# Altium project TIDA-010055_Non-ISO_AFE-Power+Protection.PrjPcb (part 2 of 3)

## Sheet TIDA-010055_Non-ISO_AFE-Power+Protection _Pg5.SchDoc: ISOLATED AFE SUPPLY , LDOs
size 431 x 279 mm; Date: Not shown in title block; ApprovedBy: Not shown in title block; CheckedBy: Not shown in title block; Author: Not shown in title block; CompanyName: Not shown in title block; DrawnBy: Sreenivasa; Engineer: Not shown in title block; Organization: Not shown in title block; Address1: Not shown in title block; Address2: Not shown in title block; Address3: Not shown in title block; Address4: Not shown in title block; DocumentNumber: 1; Revision: Use project parameter SCH_Rev; SheetNumber: 5; SheetTotal: 9; PageSetup: Record=PageOptions¦CenterHorizontal=True¦CenterVertical=True¦PrintScale=0.62¦XCorrection=1.00¦YCorrection=1.00¦PrintKind=0¦BorderSize=5000000¦LeftOffset=0¦BottomOffset=0¦Orientation=2¦PaperLength=1000¦PaperWidth=1000¦Scale=100¦PaperSource=15¦PrintQuality=600¦MediaType=1¦DitherType=10¦PrintScaleMode=1¦PaperKind=Letter
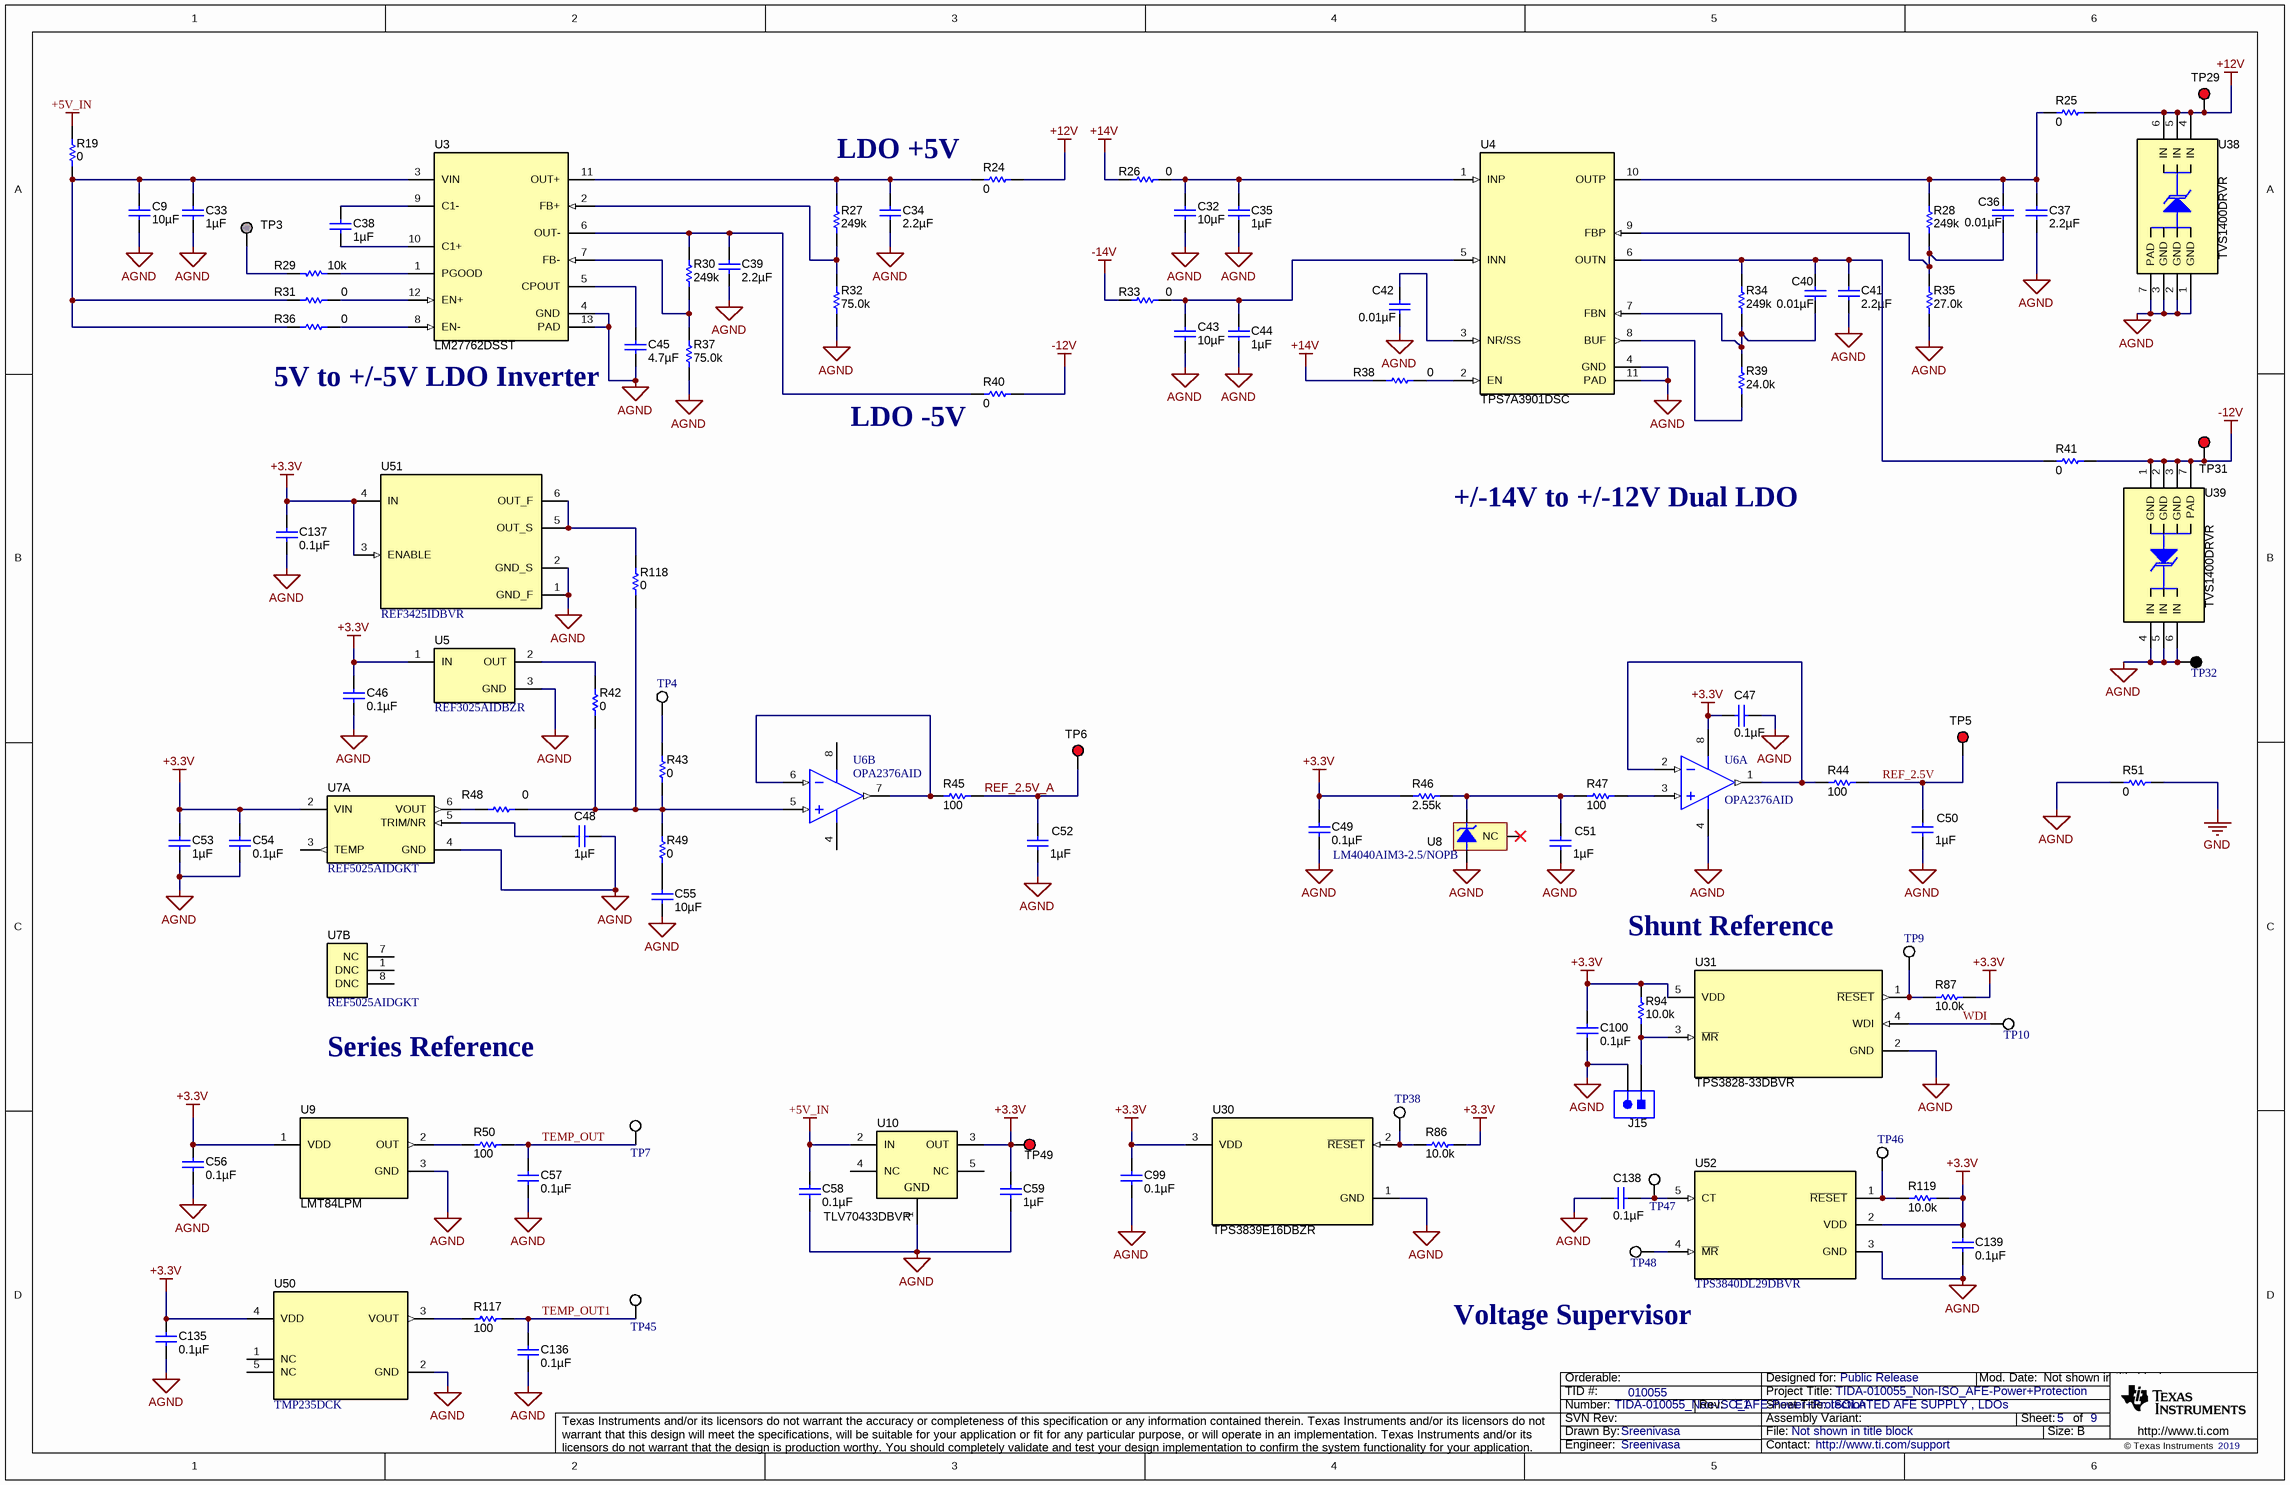
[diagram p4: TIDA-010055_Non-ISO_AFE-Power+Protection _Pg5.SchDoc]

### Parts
C9  ValueDisplayed: 10µF  [1210]
C32  ValueDisplayed: 10µF  [1210]
C33  ValueDisplayed: 1µF  [0603S]  (hidden comment: CGA3E1X7R1E105K080AC)
C34  ValueDisplayed: 2.2µF  [0805_HV]  (hidden comment: C0805C225K8RACTU)
C35  ValueDisplayed: 1µF  [0603S]  (hidden comment: CGA3E1X7R1E105K080AC)
C36  ValueDisplayed: 0.01µF  [0603]  (hidden comment: 885012206040)
C37  ValueDisplayed: 2.2µF  [0805_HV]  (hidden comment: C0805C225K8RACTU)
C38  ValueDisplayed: 1µF  [0603S]  (hidden comment: CGA3E1X7R1E105K080AC)
C39  ValueDisplayed: 2.2µF  [0805_HV]  (hidden comment: C0805C225K8RACTU)
C40  ValueDisplayed: 0.01µF  [0603]  (hidden comment: 885012206040)
C41  ValueDisplayed: 2.2µF  [0805_HV]  (hidden comment: C0805C225K8RACTU)
C42  ValueDisplayed: 0.01µF  [0603]  (hidden comment: 885012206040)
C43  ValueDisplayed: 10µF  [1210]
C44  ValueDisplayed: 1µF  [0603S]  (hidden comment: CGA3E1X7R1E105K080AC)
C45  ValueDisplayed: 4.7µF  [1206]  (hidden comment: C3216X7R1E475M160AC)
C46  ValueDisplayed: 0.1µF  [0603]  (hidden comment: 06033D104KAT2A)
C47  ValueDisplayed: 0.1µF  [0603]  (hidden comment: 06033D104KAT2A)
C48  ValueDisplayed: 1µF  [0805_HV]  (hidden comment: CL21B105KPFNNNE)
C49  ValueDisplayed: 0.1µF  [0603]  (hidden comment: 06033D104KAT2A)
C50  ValueDisplayed: 1µF  [0805_HV]  (hidden comment: C2012X7R1H105K125AE)
C51  ValueDisplayed: 1µF  [0805_HV]  (hidden comment: C2012X7R1H105K125AE)
C52  ValueDisplayed: 1µF  [0805_HV]  (hidden comment: C2012X7R1H105K125AE)
C53  ValueDisplayed: 1µF  [0805_HV]  (hidden comment: CL21B105KPFNNNE)
C54  ValueDisplayed: 0.1µF  [0603]  (hidden comment: 06033D104KAT2A)
C55  ValueDisplayed: 10µF  [0603]  (hidden comment: EMK107BBJ106MA-T)
C56  ValueDisplayed: 0.1µF  [0603]  (hidden comment: 06033D104KAT2A)
C57  ValueDisplayed: 0.1µF  [0603]  (hidden comment: 06033D104KAT2A)
C58  ValueDisplayed: 0.1µF  [0603]  (hidden comment: 06033D104KAT2A)
C59  ValueDisplayed: 1µF  [0603]  (hidden comment: CGB3B3X7R0J105K055AB)
C99  ValueDisplayed: 0.1µF  [0603]  (hidden comment: 06033D104KAT2A)
C100  ValueDisplayed: 0.1µF  [0603]  (hidden comment: 06033D104KAT2A)
C135  ValueDisplayed: 0.1µF  [0603]  (hidden comment: 06033D104KAT2A)
C136  ValueDisplayed: 0.1µF  [0603]  (hidden comment: 06033D104KAT2A)
C137  ValueDisplayed: 0.1µF  [0603]  (hidden comment: 06033D104KAT2A)
C138  ValueDisplayed: 0.1µF  [0603]  (hidden comment: 06033D104KAT2A)
C139  ValueDisplayed: 0.1µF  [0603]  (hidden comment: 06033D104KAT2A)
J15  PBC02SAAN  [Sullins_PBC02SAAN]  (value not drawn)
R19  ValueDisplayed: 0  [1206]  (hidden comment: CRCW12060000Z0EA)
R24  ValueDisplayed: 0  [0603]  (hidden comment: CRCW06030000Z0EA)
R25  ValueDisplayed: 0  [0603]  (hidden comment: CRCW06030000Z0EA)
R26  ValueDisplayed: 0  [0603]  (hidden comment: CRCW06030000Z0EA)
R27  ValueDisplayed: 249k  [0603]  (hidden comment: CRCW0603249KFKEA)
R28  ValueDisplayed: 249k  [0603]  (hidden comment: CRCW0603249KFKEA)
R29  value 10k  [0603]  (hidden comment: CRCW060310K0FKEA)
R30  ValueDisplayed: 249k  [0603]  (hidden comment: CRCW0603249KFKEA)
R31  ValueDisplayed: 0  [0603]  (hidden comment: CRCW06030000Z0EA)
R32  ValueDisplayed: 75.0k  [0603]  (hidden comment: CRCW060375K0FKEA)
R33  ValueDisplayed: 0  [0603]  (hidden comment: CRCW06030000Z0EA)
R34  ValueDisplayed: 249k  [0603]  (hidden comment: CRCW0603249KFKEA)
R35  ValueDisplayed: 27.0k  [0603]  (hidden comment: RC0603FR-0727KL)
R36  ValueDisplayed: 0  [0603]  (hidden comment: CRCW06030000Z0EA)
R37  ValueDisplayed: 75.0k  [0603]  (hidden comment: CRCW060375K0FKEA)
R38  ValueDisplayed: 0  [0603]  (hidden comment: CRCW06030000Z0EA)
R39  ValueDisplayed: 24.0k  [0603]  (hidden comment: RC0603FR-0724KL)
R40  ValueDisplayed: 0  [0603]  (hidden comment: CRCW06030000Z0EA)
R41  ValueDisplayed: 0  [0603]  (hidden comment: CRCW06030000Z0EA)
R42  value 0  [0603]  (hidden comment: CRCW06030000Z0EA)
R43  value 0  [0603]  (hidden comment: CRCW06030000Z0EA)
R44  ValueDisplayed: 100  [0603]  (hidden comment: CRCW0603100RFKEA)
R45  ValueDisplayed: 100  [0603]  (hidden comment: CRCW0603100RFKEA)
R46  ValueDisplayed: 2.55k  [0603]  (hidden comment: CRCW06032K55FKEA)
R47  ValueDisplayed: 100  [0603]  (hidden comment: CRCW0603100RFKEA)
R48  value 0  [0603]  (hidden comment: CRCW06030000Z0EA)
R49  value 0  [0603]  (hidden comment: CRCW06030000Z0EA)
R50  ValueDisplayed: 100  [0603]  (hidden comment: CRCW0603100RFKEA)
R51  ValueDisplayed: 0  [1206]  (hidden comment: RC1206JR-070RL)
R86  ValueDisplayed: 10.0k  [0603]  (hidden comment: RC0603FR-0710KL)
R87  ValueDisplayed: 10.0k  [0603]  (hidden comment: RC0603FR-0710KL)
R94  ValueDisplayed: 10.0k  [0603]  (hidden comment: RC0603FR-0710KL)
R117  ValueDisplayed: 100  [0603]  (hidden comment: CRCW0603100RFKEA)
R118  value 0  [0603]  (hidden comment: CRCW06030000Z0EA)
R119  ValueDisplayed: 10.0k  [0603]  (hidden comment: RC0603FR-0710KL)
TP3  Pogo Pad  [PogoPad]  (value not drawn)  (no BOM)
TP4  5002  [Keystone5002]  (value not drawn)
TP5  5000  [Keystone5000]  (value not drawn)
TP6  5000  [Keystone5000]  (value not drawn)
TP7  5002  [Keystone5002]  (value not drawn)
TP9  5002  [Keystone5002]  (value not drawn)
TP10  5002  [Keystone5002]  (value not drawn)
TP29  5000  [Keystone5000]  (value not drawn)
TP31  5000  [Keystone5000]  (value not drawn)
TP32  5001  [Keystone5001]  (value not drawn)
TP38  5002  [Keystone5002]  (value not drawn)
TP45  5002  [Keystone5002]  (value not drawn)
TP46  5002  [Keystone5002]  (value not drawn)
TP47  5002  [Keystone5002]  (value not drawn)
TP48  5002  [Keystone5002]  (value not drawn)
TP49  5000  [Keystone5000]  (value not drawn)
U3  LM27762DSST  [DSS0012B]
U4  TPS7A3901DSC  [DSC0010J]
U5  REF3025AIDBZR  [DBZ0003A_N]
U6  OPA2376AID  [D0008A_N]  (parts A,B of 2)
U7  REF5025AIDGKT  [DGK0008A_N]  (parts A,B of 2)
U8  LM4040AIM3-2.5/NOPB  [MF03A_N]
U9  LMT84LPM  [LP0003A_straight]
U10  TLV70433DBVR  [DBV0005A_N]
U30  TPS3839E16DBZR  [DBZ0003A_N]
U31  TPS3828-33DBVR  [DBV0005A_N]
U38  TVS1400DRVR  [DRV0006A]
U39  TVS1400DRVR  [DRV0006A]
U50  TMP235DCK  [DCK0005A_N]
U51  REF3425IDBVR  [DBV0006A_N]
U52  TPS3840DL29DBVR  [DBV0005A_N]

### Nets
+3.3V: C46.1 C47.2 C49.2 C53.1 C54.1 C56.2 C59.1 C99.1 C100.1 C135.2 C137.1 C139.1 R46.1 R86.1 R87.1 R94.1 R119.1 TP49.1 U5.1(IN) U6.8(V+) U7.2(VIN) U9.1(VDD) U10.3(OUT) U30.3(VDD) U31.5(VDD) U50.4(VDD) U51.3(ENABLE) U51.4(IN) U52.2(VDD)
+5V_IN: C58.1 R19.2 U10.2(IN)
+12V: R24.2 R25.2 TP29.1 U38.4(IN) U38.5(IN) U38.6(IN)
+14V: R26.1 R38.1
-12V: R40.2 R41.2 TP31.1 U39.1(GND) U39.2(GND) U39.3(GND) U39.7(PAD)
-14V: R33.1
AGND: C9.1 C32.1 C33.2 C34.2 C35.2 C37.2 C39.2 C41.2 C42.2 C43.1 C44.2 C45.2 C46.2 C47.1 C48.2 C49.1 C50.2 C51.2 C52.2 C53.2 C54.2 C55.2 C56.1 C57.1 C58.2 C59.2 C99.2 C100.2 C135.1 C136.1 C137.2 C138.1 C139.2 J15.2 R32.1 R35.1 R37.1 R51.1 TP32.1 U3.4(GND) U3.13(PAD) U4.4(GND) U4.11(PAD) U5.3(GND) U6.4(V-) U7.4(GND) U8.2(-V) U9.3(GND) U10.1(GND) U30.1(GND) U31.2(GND) U38.1(GND) U38.2(GND) U38.3(GND) U38.7(PAD) U39.4(IN) U39.5(IN) U39.6(IN) U50.2(GND) U51.1(GND_F) U51.2(GND_S) U52.3(GND)
GND: R51.2
REF_2.5V: C50.1 R44.2 TP5.1
REF_2.5V_A: C52.1 R45.2 TP6.1
TEMP_OUT: C57.2 R50.2 TP7.1
TEMP_OUT1: C136.2 R117.2 TP45.1
WDI: TP10.1 U31.4(WDI)
NetC9_2: C9.2 C33.1 R19.1 R31.1 R36.1 U3.3(VIN)
NetC32_2: C32.2 C35.1 R26.2 U4.1(INP)
NetC34_1: C34.1 R24.1 R27.2 U3.11(OUT+)
NetC36_1: C36.1 C37.1 R25.1 R28.2 U4.10(OUTP)
NetC36_2: C36.2 R28.1 R35.2 U4.9(FBP)
NetC38_1: C38.1 U3.9(C1-)
NetC38_2: C38.2 U3.10(C1+)
NetC39_1: C39.1 R30.2 R40.1 U3.6(OUT-)
NetC40_1: C40.1 C41.1 R34.2 R41.1 U4.6(OUTN)
NetC40_2: C40.2 R34.1 R39.2 U4.7(FBN)
NetC42_1: C42.1 U4.3(NR/SS)
NetC43_2: C43.2 C44.1 R33.2 U4.5(INN)
NetC45_1: C45.1 U3.5(CPOUT)
NetC48_1: C48.1 U7.5(TRIM/NR)
NetC51_1: C51.1 R46.2 R47.1 U8.1(+V)
NetC55_1: C55.1 R49.2
NetC138_2: C138.2 TP47.1 U52.5(CT)
NetJ15_1: J15.1 R94.2 U31.3(~{MR})
NetR27_1: R27.1 R32.2 U3.2(FB+)
NetR29_1: R29.1 TP3.1
NetR29_2: R29.2 U3.1(PGOOD)
NetR30_1: R30.1 R37.2 U3.7(FB-)
NetR31_2: R31.2 U3.12(EN+)
NetR36_2: R36.2 U3.8(EN-)
NetR38_2: R38.2 U4.2(EN)
NetR39_1: R39.1 U4.8(BUF)
NetR42_1: R42.1 U5.2(OUT)
NetR42_2: R42.2 R43.2 R48.2 R49.1 R118.2 U6.5(IN_B+)
NetR43_1: R43.1 TP4.1
NetR44_1: R44.1 U6.1(OUT_A) U6.2(IN_A-)
NetR45_1: R45.1 U6.6(IN_B-) U6.7(OUT_B)
NetR47_2: R47.2 U6.3(IN_A+)
NetR48_1: R48.1 U7.6(VOUT)
NetR50_1: R50.1 U9.2(OUT)
NetR86_2: R86.2 TP38.1 U30.2(~{RESET})
NetR87_2: R87.2 TP9.1 U31.1(~{RESET})
NetR117_1: R117.1 U50.3(VOUT)
NetR118_1: R118.1 U51.5(OUT_S) U51.6(OUT_F)
NetR119_2: R119.2 TP46.1 U52.1(~{RESET})
NetTP48_1: TP48.1 U52.4(~{MR})

Not connected (* = marked no-connect by the designer): U7 1(DNC) 3(TEMP) 7(NC) 8(DNC); U8 3(NC)*; U10 4(NC) 5(NC); U50 1(NC) 5(NC)

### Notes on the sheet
- LDO +5V
- (near C45) 5V to +/-5V LDO Inverter
- (near R40) LDO -5V
- +/-14V to +/-12V Dual LDO
- Shunt Reference
- (near U7) Series Reference
- Voltage Supervisor

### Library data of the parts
C9 C32 C43 = GMK325AB7106MM-T: CAP, CERM, 10µF ±10% 35V Ceramic Capacitor X7R 1210; PartNumber: GMJ325KB7106KMHP; Manufacturer: Taiyo Yuden; Polarized: N; Value: 10uF; U/M: EA; Cap_F: 0.00001; Tolerance_%: 20; Value1: Unknown; VDC_V: 35; TaMin_C: -55; TaMax_C: 125
C33 C35 C38 C44 = GRM188R71E105KA12D: CAP, CERM, 1 µF, 25 V, +/- 10%, X7R, 0603; Manufacturer: TDK Corporation; Polarized: N; CompType: Capacitor; Value: 1uF; U/M: EA; Cap_F: 0.000001; Tolerance_%: 10; Value1: Unknown; VDC_V: 25; Value2: 25V; TaMin_C: -55; TaMax_C: 125; Cap_Case: 0603; AEC Category: Q200
C34 C37 C39 C41 = C0805C225K8RACTU: CAP, CERM, 2.2uF, 10V, +/-10%, X7R, 0805; Manufacturer: Kemet; Polarized: N; CompType: Capacitor; U/M: EA; Cap_F: 0.0000022; Tolerance_%: 10; ESR_Ohm: 0.008; Value1: 0.008 ohm; IRMS_A: 15.55; TaMin_C: -55; TaMax_C: 125; Cap_Case: 0805
C36 C40 C42 = 885012206040: CAP, CERM, 0.01 µF, 16 V,+/- 10%, X7R, 0603; Manufacturer: Wurth Elektronik; Polarized: N; CompType: Capacitor; Value: 0.01uF; U/M: EA; Cap_F: 0.00000001; Tolerance_%: 10; VDC_V: 16; Value2: 16V; TaMin_C: -55; TaMax_C: 125; SizeArea_mm2: 1.28; SizeAreaWB_mm2: 4.68; SizeX_mm: 1.6; SizeY_mm: 0.8; SizeZ_mm: 1; AEC Category: Q200; Green_Lifecycle: Active; Green_REACh: Passed
C45 = C3216X7R1E475M: CAP, CERM, 4.7 µF, 25 V, +/- 20%, X7R, 1206; Manufacturer: TDK; Polarized: N; CompType: Capacitor; Value: 4.7uF; U/M: EA; Cap_F: 0.0000047; Tolerance_%: 20; ESR_ohm: 0.0063; Value1: 0.0063 ohm; VDC_V: 25; Value2: 25V; TaMin_C: -55; TaMax_C: 125
C46 C54 C58 C99 C100 C137-C139 = 06033D104KAT2A: CAP, CERM, 0.1 µF, 25 V,+/- 10%, X5R, 0603; Manufacturer: AVX; Polarized: N; CompType: Capacitor; Value: 0.1uF; U/M: EA; Cap_F: 0.0000001; Tolerance_%: 10; ESR_ohm: 0.048; Value1: 0.048 ohm; VDC_V: 25; Value2: 25V; IRMS_A: 0.53; TaMin_C: -55; TaMax_C: 85; SizeArea_mm2: 1.28; SizeAreaWB_mm2: 4.68; SizeX_mm: 1.6; SizeY_mm: 0.8; SizeZ_mm: 1; AEC Category: Q200; Green_Lifecycle: Active; Green_REACh: Passed
C47 C49 C56 C57 C135 C136 = 06033D104KAT2A: CAP, CERM, 0.1 µF, 25 V,+/- 10%, X5R, 0603; Manufacturer: AVX; Polarized: N; CompType: Capacitor; Value: 0.1uF; U/M: EA; Cap_F: 0.0000001; Tolerance_%: 10; ESR_ohm: 0.048; Value1: 0.048 ohm; VDC_V: 25; Value2: 25V; IRMS_A: 0.53; TaMin_C: -55; TaMax_C: 85; AEC Category: Q200; SizeArea_mm2: 1.28; SizeAreaWB_mm2: 4.68; SizeX_mm: 1.6; SizeY_mm: 0.8; SizeZ_mm: 1; Green_Lifecycle: Active; Green_REACh: Passed
C48 C53 = C0805C105K8RACTU: CAP, CERM, 1uF, 10V, +/-10%, X7R, 0805; Manufacturer: Samsung Electro-Mechanics; Polarized: N; CompType: Capacitor; U/M: EA; Cap_F: 0.000001; Tolerance_%: 10; ESR_Ohm: 0.015; Value1: 0.015 ohm; IRMS_A: 8.19; TaMin_C: -55; TaMax_C: 125; Cap_Case: 0805
C50-C52 = GRM21BR71H105KA12L: CAP, CERM, 1 µF, 50 V, +/- 10%, X7R, 0805; Manufacturer: MuRata; Polarized: N; CompType: Capacitor; Value: 1uF; U/M: EA; Cap_F: 0.000001; Tolerance_%: 10; Value1: Unknown; VDC_V: 50; Value2: 50V; TaMin_C: -55; TaMax_C: 125; Cap_Case: 0805; AEC Category: Q200
C55 = EMK107BBJ106MA-T: CAP, CERM, 10uF, 16V, +/-20%, X5R, 0603; Manufacturer: Taiyo Yuden; Polarized: N; CompType: Capacitor; U/M: EA; Cap_F: 0.00001; Tolerance_%: 20; Value1: Unknown; VDC_V: 16; TaMin_C: -55; TaMax_C: 85
C59 = CL10B105KQ8NNNC: CAP, CERM, 1 µF, 6.3 V, +/- 10%, X7R, 0603; Manufacturer: TDK Corporation; Polarized: N; CompType: Capacitor; Value: 1uF; U/M: EA; Cap_F: 0.000001; Tolerance_%: 10; Value1: Unknown; VDC_V: 6.3; Value2: 6.3V; TaMin_C: -55; TaMax_C: 125; SizeArea_mm2: 1.28; SizeAreaWB_mm2: 4.68; SizeX_mm: 1.6; SizeY_mm: 0.8; SizeZ_mm: 1; AEC Category: Q200
J15 = PBC02SAAN: Header, 100mil, 2x1, Gold, TH; Manufacturer: Sullins Connector Solutions; SymbolCreator: a0412235; Pitch_mm: 2.54; Gender: Male; Shrouded: N; Row_Count: 1; Current_A: 3; Voltage_V: 1800; Cert_UL: Y
R19 = CRCW12060000Z0EA: RES, 0, 5%, 0.25 W, 1206; Manufacturer: Vishay-Dale; CompType: Resistor; Value: 0; Value_Code: 0000; Tolerance_%: 5; Power_W: 0.25; Value2: 0.25W; VDC_V: 200; TempCo: 200 ppm/C; SizeArea_mm2: 5.12; SizeX_mm: 3.2; SizeY_mm: 1.6; SizeZ_mm: 1.35; EIA_Code: E24; U/M: EA; AEC Category: Q200
R24-R26 R31 R33 R36 R38 R40 R41 = CRCW06030000Z0EA: RES, 0, 5%, 0.1 W, 0603; Manufacturer: Vishay-Dale; CompType: Resistor; Value: 0; Value_Code: 0000; Tolerance_%: 5; Power_W: 0.1; Value2: 0.1W; VDC_V: 75; TempCo: 200 ppm/C; EIA_Code: E24; U/M: EA
R27 R28 R30 R34 = CRCW0603249KFKEA: RES, 249 k, 1%, 0.1 W, 0603; Manufacturer: Vishay-Dale; CompType: Resistor; Value: 249k; Res_ohm: 249000; Tolerance_%: 1; Power_W: 0.1; Value2: 0.1W; VDC_V: 75; TempCo: 100 ppm/C; SizeArea_mm2: 1.28; SizeX_mm: 1.6; SizeY_mm: 0.8; EIA_Code: E96; U/M: EA; AEC Category: Q200
R29 = RNCF0603TKY10K0: RES, 10.0k ohm, 1%, 0.1W, 0603; Manufacturer: Stackpole Electronics Inc; CompType: Resistor; Res_ohm: 10000; Value_Code: 10k0; Tolerance_%: 0.01; Value1: 0.01%; Power_W: 0.063; Value2: 0.063W; VDC_V: 50; TempCo: 5 ppm/C; U/M: EA
R32 R37 = CRCW060375K0FKEA: RES, 75.0 k, 1%, 0.1 W, 0603; Manufacturer: Vishay-Dale; CompType: Resistor; Value: 75.0k; Res_ohm: 75000; Value_Code: 75k0; Tolerance_%: 1; Power_W: 0.1; Value2: 0.1W; VDC_V: 75; TempCo: 100 ppm/C; SizeArea_mm2: 1.28; SizeX_mm: 1.6; SizeY_mm: 0.8; EIA_Code: E96; U/M: EA; AEC Category: Q200
R35 = RC0603FR-0727KL: RES, 27.0 k, 1%, 0.1 W, 0603; Manufacturer: Yageo America; CompType: Resistor; Value: 27.0k; Res_ohm: 27000; Value_Code: 27k0; Tolerance_%: 1; Power_W: 0.1; Value2: 0.1W; VDC_V: 150; TempCo: 200 ppm/C; SizeArea_mm2: 1.28; SizeX_mm: 1.6; SizeY_mm: 0.8; U/M: EA; AEC Category: Q200; Green_Lifecycle: Active; Green_REACh: Passed
R39 = RC0603FR-0724KL: RES, 24.0 k, 1%, 0.1 W, 0603; Manufacturer: Yageo America; CompType: Resistor; Value: 24.0k; Res_ohm: 24000; Value_Code: 24k0; Tolerance_%: 1; Power_W: 0.1; Value2: 0.1W; VDC_V: 150; TempCo: 200 ppm/C; SizeArea_mm2: 1.28; SizeX_mm: 1.6; SizeY_mm: 0.8; U/M: EA; AEC Category: Q200; Green_Lifecycle: Active; Green_REACh: Passed
R42 R43 R48 R49 R118 = CRCW06030000Z0EA: RES, 0 ohm, 5%, 0.1W, 0603; Manufacturer: Vishay-Dale; CompType: Resistor; Value_Code: 0000; Tolerance_%: 5; Power_W: 0.1; VDC_V: 75; TempCo: 200 ppm/C; EIA_Code: E24; U/M: EA
R44 R45 R47 R50 R117 = CRCW0603100RFKEA: RES, 100, 1%, 0.1 W, 0603; Manufacturer: Vishay-Dale; CompType: Resistor; Value: 100; Value_Code: 100R; Tolerance_%: 1; Power_W: 0.1; Value2: 0.1W; VDC_V: 75; TempCo: 100 ppm/C; EIA_Code: E96; U/M: EA; AEC Category: Q200
R46 = CRCW06032K55FKEA: RES, 2.55 k, 1%, 0.1 W, 0603; Manufacturer: Vishay-Dale; CompType: Resistor; Value: 2.55k; Res_ohm: 2550; Value_Code: 2k55; Tolerance_%: 1; Power_W: 0.1; Value2: 0.1W; VDC_V: 75; TempCo: 100 ppm/C; EIA_Code: E96; U/M: EA; AEC Category: Q200
R51 = RC1206JR-070RL: RES, 0, 5%, 0.25 W, 1206; Manufacturer: Yageo America; CompType: Resistor; Value: 0; Value_Code: 0000; Tolerance_%: 5; Power_W: 0.25; Value2: 0.25W; VDC_V: 200; TempCo: 200 ppm/C; SizeArea_mm2: 5.12; SizeX_mm: 3.2; SizeY_mm: 1.6; SizeZ_mm: 1.35; EIA_Code: E24; U/M: EA; AEC Category: Q200; Green_Lifecycle: Active; Green_REACh: Passed
R86 R87 R94 R119 = RC0603FR-0710KL: RES, 10.0 k, 1%, 0.1 W, 0603; Manufacturer: Yageo America; CompType: Resistor; Value: 10.0k; Res_ohm: 10000; Value_Code: 10k0; Tolerance_%: 1; Power_W: 0.1; Value2: 0.1W; VDC_V: 150; TempCo: 200 ppm/C; SizeArea_mm2: 1.28; SizeX_mm: 1.6; SizeY_mm: 0.8; EIA_Code: E96; U/M: EA; AEC Category: Q200; Green_Lifecycle: Active; Green_REACh: Passed
TP3 = PogoPad: Pad for Pogo Pin Connector; SymbolCreator: codlsc
TP4 TP7 TP9 TP10 TP38 TP45-TP48 = 5002: Test Point, Miniature, White, TH; Manufacturer: Keystone; CompType: Test Point Loop; ContactFinish: Silver; Green_Lifecycle: Active; Green_REACh: Passed
TP5 TP6 TP29 TP31 TP49 = 5000: Test Point, Miniature, Red, TH; Manufacturer: Keystone; CompType: Test Point Loop; ContactFinish: Silver
TP32 = 5001: Test Point, Miniature, Black, TH; Manufacturer: Keystone; CompType: Test Point Loop; ContactFinish: Silver; Green_Lifecycle: Active; Green_REACh: Passed
U3 = LM27762DSSR: Low-Noise Regulated Switched-Capacitor Voltage Inverter and Positive LDO, DSS0012B; Manufacturer: Texas Instruments; SymbolCreator: Altium; SizeArea_mm2: 6; SizeAreaWB_mm2: 12; SizeX_mm: 2; SizeY_mm: 3; SizeZ_mm: 0.8; CompType: IC; U/M: EA
U4 = TPS7A3901DSC: Wide-VIN (±33 V), 150-mA, Spilt-Rail Output, Positive and Negative LDO Voltage Regulator with Startup Tracking, DSC0010J; Manufacturer: Texas Instruments; SymbolCreator: Altium; SizeArea_mm2: 9; SizeAreaWB_mm2: 16; SizeX_mm: 3; SizeZ_mm: 0.8; CompType: IC; U/M: EA
U5 = REF3025AIDBZR: 2.5 V, 50 ppm / degC, 50 uA Series (Bandgap) Voltage Reference, -40 to 125 degC, 3-pin SOT-23 (DBZ), Green (RoHS & no Sb/Br); Manufacturer: Texas Instruments; Alternate PartNumber: Equivalent; Initial Accuracy @ 25/deg C(%): 0.2; Iq(Max)(uA): 50; Rating: Catalog; SubFamily: Series Voltage Reference; Temp Coeff(Typ)(ppm/ degree C): 20; VI(Max)(V): 5.5; VI(Min)(V): 2.501; VO(V): 2.5
U6 = CMP-0040811-1: Precision, Low Noise, Low Quiescent Current Operational Amplifier, 2 to 5.5 V, -40 to 125 degC, 8-pin SOIC (D8), Green (RoHS & no Sb/Br); Manufacturer: Texas Instruments; Total Supply Voltage(Min)(+5V is 5, +/-5V is 10): 2; Vn at 1kHz(Typ)(nV/rtHz): 7.5; CMRR(Min)(dB): 76; Sub Family: Low Input Bias Current Amp (<=10pA), Low Noise Amp (<=10nV/rtHz), Low Offset Voltage Amplifier (<=500uV), Low Supply Voltage Amplifier (<=2.7V), Precision Amplifier; Iq per channel(Max)(mA): 0.95; Total Supply Voltage(Max)(+5V is 5, +/-5V is 10): 5.5; Vio (25C)(Max)(mV): 0.025; IIB(Max)(pA): 10; Offset Drift(Typ)(uV/C): 0.32
U7 = REF5025AIDGKT: Low Noise, Very Low Drift, Precision Voltage Reference, -40 to 125 degC, 8-pin MSOP(DGK), Green (RoHS & no Sb/Br); Manufacturer: Texas Instruments; Alternate PartNumber: Equivalent; Initial Accuracy @ 25/deg C(%): 0.05; Iout/Iz(Max)(mA): 10; Iq(Max)(uA): 1000; Rating: Military; SubFamily: Series Voltage Reference; Temp Coeff(Max)(ppm/ degree C): 3; VI(Max)(V): 18; VI(Min)(V): 2.7; VO(V): 2.5
U8 = LM4040AIM3-2.5/NOPB: Precision Micropower Shunt Voltage Reference, 3-pin SOT-23, Pb-Free; Manufacturer: Texas Instruments; PackageTopMarking: R2A*XTT; PowerWise: N; CompType: Voltage Reference IC
U9 = CMP-0076506-2: 1.5V-Capable, 10 uA Analog Output Temperature Sensor in SC70 and TO-92, LP0003A (TO-92-3); Manufacturer: Texas Instruments; SizeZ_mm: 9.33; SizeX_mm: 3.68; SizeY_mm: 5.0; SizeArea_mm2: 18.4; CompType: IC; U/M: EA; SizeAreaWB_mm2: 39.76
U10 = TLV70433DBVR: Single Output LDO, 150 mA, Fixed 3.3 V Output, 2.5 to 24 V Input, with Ultra-Low IQ, 5-pin SOT-23 (DBV), -40 to 125 degC, Green (RoHS & no Sb/Br); Manufacturer: Texas Instruments; Alternate PartNumber: Equivalent; Accuracy(%): 2; Fixed Output Options(V): 3.3; Iout(Max)(A): 0.15; Iq(Typ)(mA): 0.003; SubFamily: Single Channel LDO; Vdo(Typ)(mV): 400; Vin(Max)(V): 24; Vin(Min)(V): 2.5
U30 = CMP-0074269-1: 150-nA, Ultralow Power, Supply Voltage Monitor, DBZ0003A (SOT-23-3); Alternate PartNumber: TPS3839E16DBZT; Alternate Manufacturer: Texas Instruments; SizeAreaWB_mm2: 14.0; SizeZ_mm: 1.12; SizeX_mm: 2.5; SizeY_mm: 3.0; SizeArea_mm2: 7.5; CompType: IC
U31 = CMP-0067355-1: Voltage Monitor With Watchdog Timer, DBV0005A (SOT-23-5); Alternate PartNumber: TPS3828-33DBVT; Alternate Manufacturer: Texas Instruments; SizeAreaWB_mm2: 14.82; U/M: EA; SizeZ_mm: 1.45; SizeX_mm: 2.8; SizeY_mm: 2.9; SizeArea_mm2: 8.12; CompType: IC
U38 U39 = CMP-0077836-1: 14-V Precision Surge Protection Clamp, DRV0006A (WSON-6); Alternate Manufacturer: Texas Instruments; SizeAreaWB_mm2: 9.0; SizeZ_mm: 0.8; SizeX_mm: 2.0; SizeArea_mm2: 4.0; CompType: IC; AEC Qualified: N; AEC Category: Q200
U50 = CMP-0013250-1: TMP235DCK, DCK0005A (SOT-5); Manufacturer: Texas Instruments; SizeZ_mm: 1.1; SizeX_mm: 2.1; SizeY_mm: 2; SizeArea_mm2: 4.2; CompType: IC; U/M: EA; SizeAreaWB_mm2: 9.3
U51 = CMP-0083672-1: 2.5V Low-Drift Low-Power Small-Footprint Series Voltage Reference, DBV0006A (SOT-23-6); Alternate Manufacturer: Texas Instruments; SizeAreaWB_mm2: 14.82; Rating: Catalog; SizeZ_mm: 1.45; SizeX_mm: 2.8; SizeY_mm: 2.9; SizeArea_mm2: 8.12; CompType: IC; AEC Qualified: N; AEC Category: Q200
U52 = CMP-0084478-1: Nano Power, Wide VIN Voltage Detector with Programmable Delay, DBV0005A (SOT-23-5); Manufacturer: Texas Instruments; SizeZ_mm: 1.45; SizeAreaWB_mm2: 14.82; SizeY_mm: 2.9; AEC Qualified: N; CompType: IC; SizeArea_mm2: 8.12; SizeX_mm: 2.8; AEC Category: Q200

## Sheet TIDA-010055_Non-ISO_AFE-Power+Protection _Pg6.SchDoc: +24V NON-ISOLATED DC-DC + 24V POWER MODULE
size 431 x 279 mm; Date: Not shown in title block; ApprovedBy: Not shown in title block; CheckedBy: Not shown in title block; Author: Not shown in title block; CompanyName: Not shown in title block; DrawnBy: Sreenivasa; Engineer: Not shown in title block; Organization: Not shown in title block; Address1: Not shown in title block; Address2: Not shown in title block; Address3: Not shown in title block; Address4: Not shown in title block; DocumentNumber: 1; Revision: Use project parameter SCH_Rev; SheetNumber: 6; SheetTotal: 9; PageSetup: Record=PageOptions¦CenterHorizontal=True¦CenterVertical=True¦PrintScale=0.62¦XCorrection=1.00¦YCorrection=1.00¦PrintKind=0¦BorderSize=5000000¦LeftOffset=0¦BottomOffset=0¦Orientation=2¦PaperLength=1000¦PaperWidth=1000¦Scale=100¦PaperSource=15¦PrintQuality=600¦MediaType=1¦DitherType=10¦PrintScaleMode=1¦PaperKind=Letter
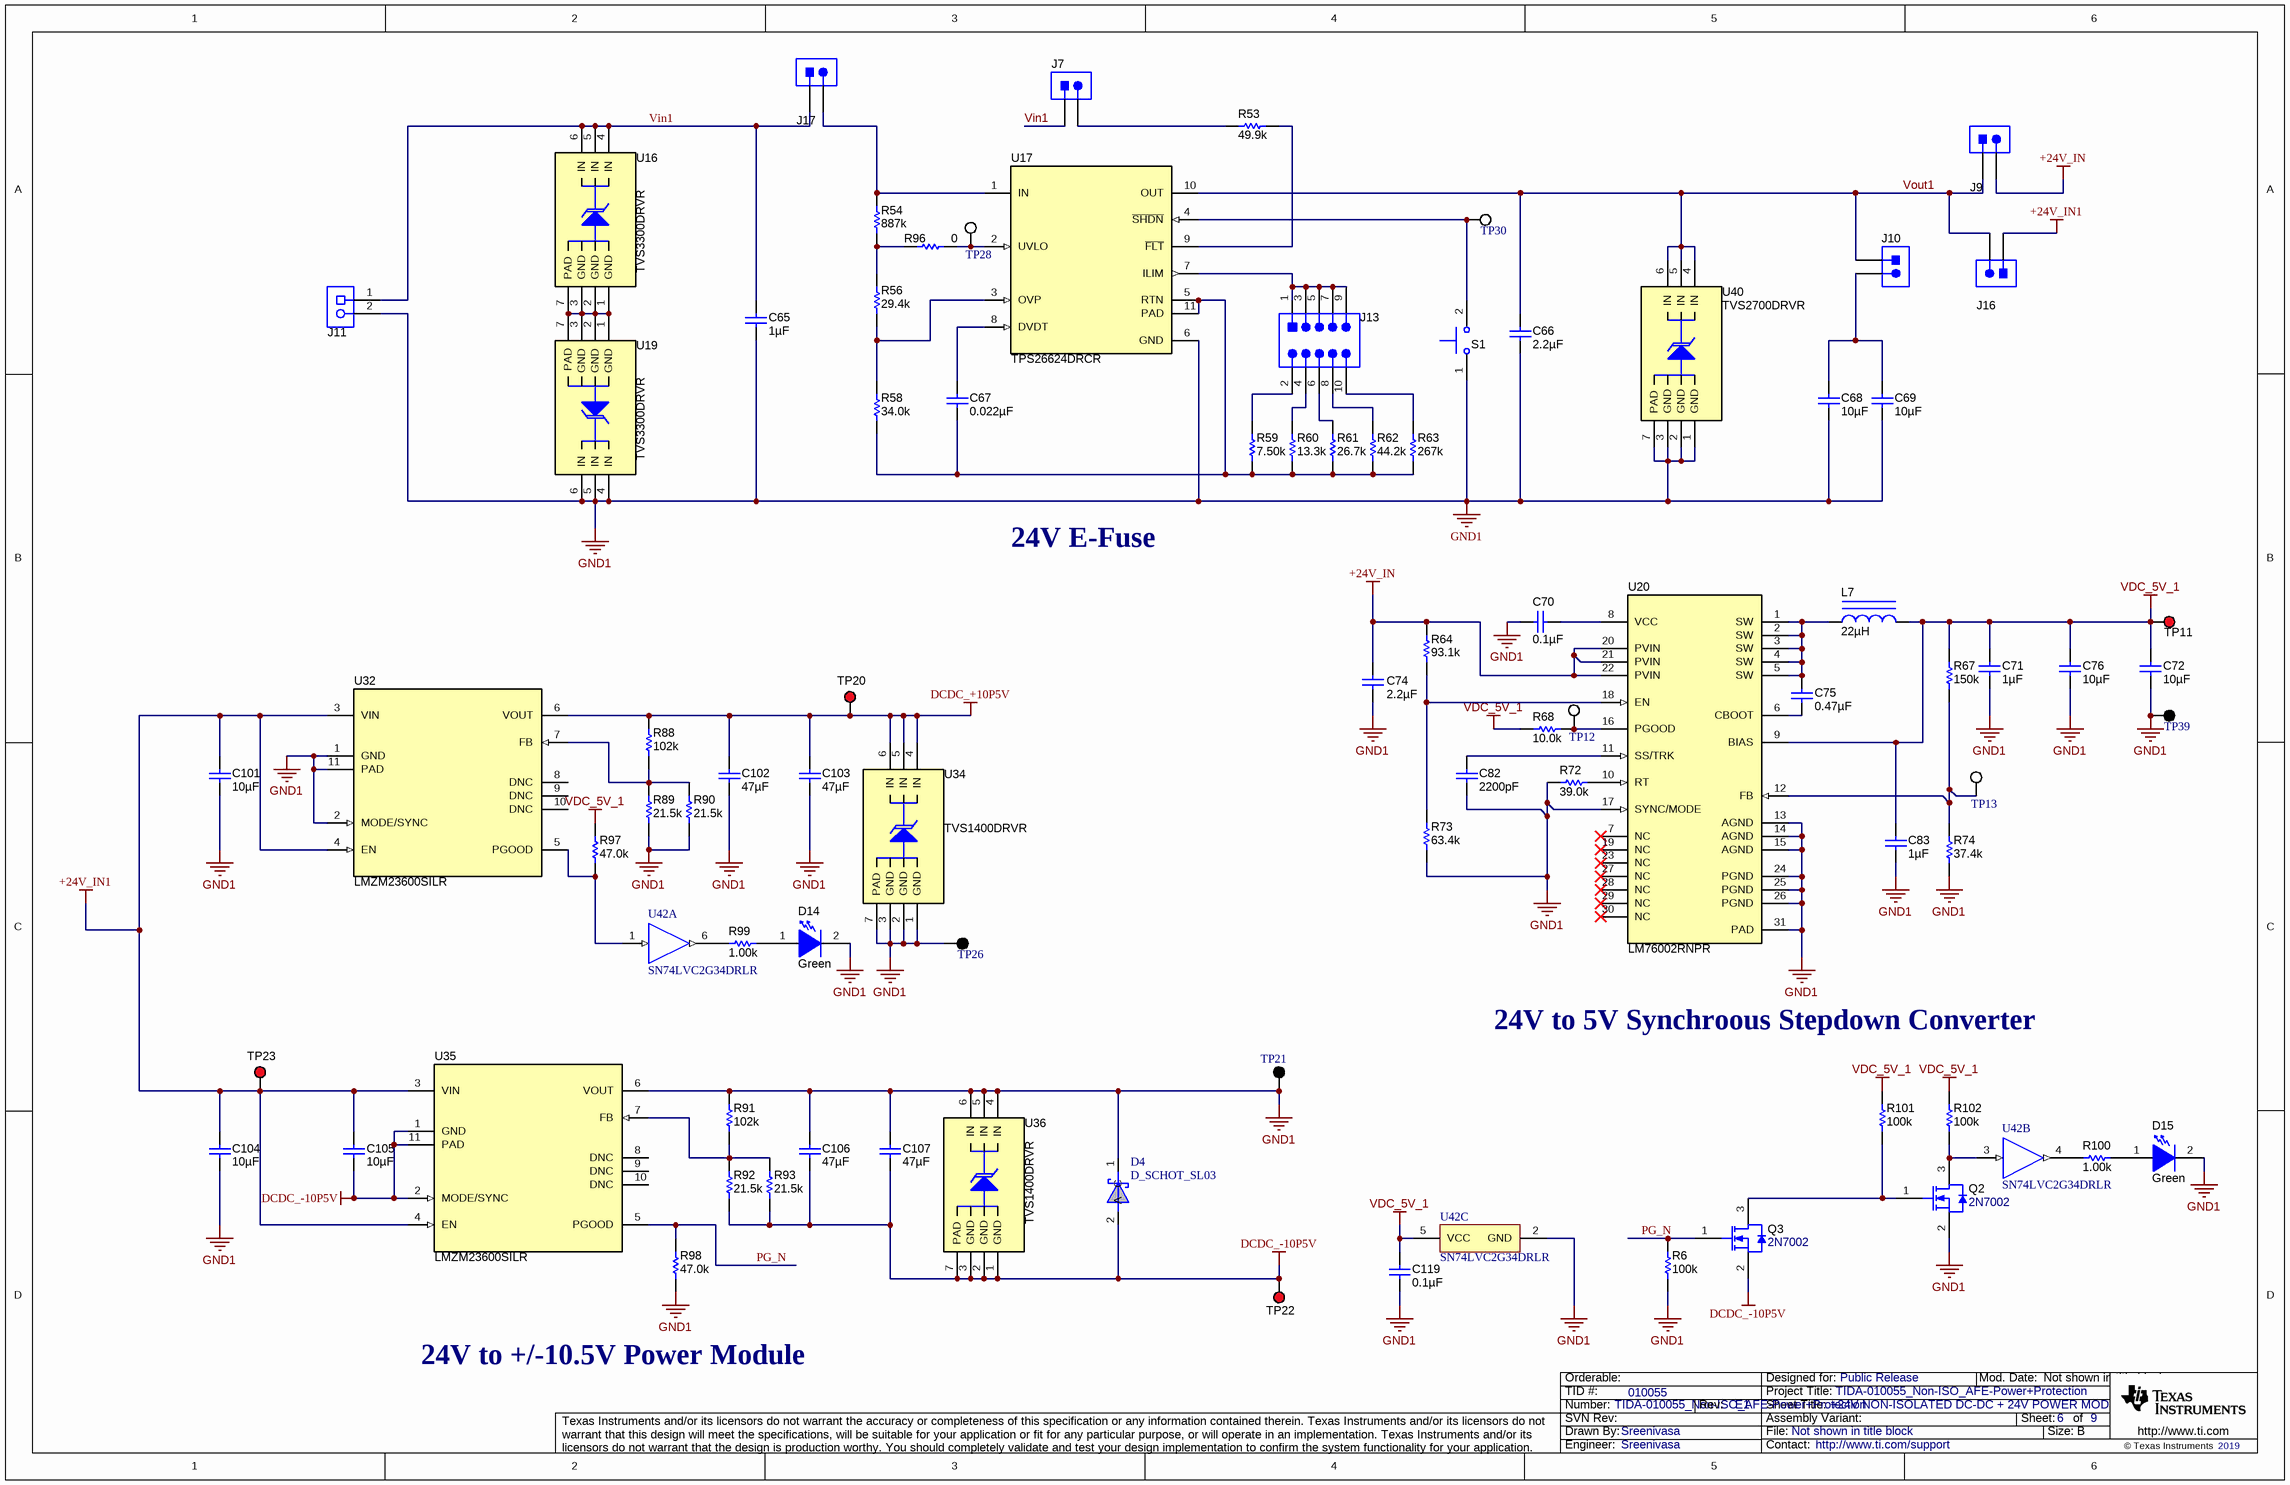
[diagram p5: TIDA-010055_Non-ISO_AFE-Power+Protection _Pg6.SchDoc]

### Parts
C65  ValueDisplayed: 1µF  [1206_180M]  (hidden comment: C3216X7R2A105K160AA)
C66  ValueDisplayed: 2.2µF  [1210_270]  (hidden comment: C3225X7R2A225K230AB)
C67  ValueDisplayed: 0.022µF  [0603]  (hidden comment: C0603C223K4RACTU)
C68  ValueDisplayed: 10µF  [1210_270]  (hidden comment: C3225X7S1H106M250AB)
C69  ValueDisplayed: 10µF  [1210_270]  (hidden comment: C3225X7S1H106M250AB)
C70  ValueDisplayed: 0.1µF  [0603]  (hidden comment: C0603X124K5RAC7867)
C71  ValueDisplayed: 1µF  [0603S]  (hidden comment: CGA3E1X7R1E105K080AC)
C72  ValueDisplayed: 10µF  [0603]  (hidden comment: EMK107BBJ106MA-T)
C74  ValueDisplayed: 2.2µF  [1206]  (hidden comment: C3216X7S2A225K160AB)
C75  ValueDisplayed: 0.47µF  [0805_HV]  (hidden comment: GCM21BR71H474KA55L)
C76  ValueDisplayed: 10µF  [0603]  (hidden comment: EMK107BBJ106MA-T)
C82  ValueDisplayed: 2200pF  [0603]  (hidden comment: GRM1885C1H222JA01D)
C83  ValueDisplayed: 1µF  [0603]  (hidden comment: UMK107BJ105KA-T)
C101  ValueDisplayed: 10µF  [1210_270]  (hidden comment: C3225X7S1H106M250AB)
C102  ValueDisplayed: 47µF  [1206]  (hidden comment: EMK316BBJ476ML-T)
C103  ValueDisplayed: 47µF  [1206]  (hidden comment: EMK316BBJ476ML-T)
C104  ValueDisplayed: 10µF  [1210_270]  (hidden comment: C3225X7S1H106M250AB)
C105  ValueDisplayed: 10µF  [1210_270]  (hidden comment: C3225X7S1H106M250AB)
C106  ValueDisplayed: 47µF  [1206]  (hidden comment: EMK316BBJ476ML-T)
C107  ValueDisplayed: 47µF  [1206]  (hidden comment: EMK316BBJ476ML-T)
C119  ValueDisplayed: 0.1µF  [0603]  (hidden comment: 06033D104KAT2A)
D4  D_SCHOT_SL03  [DO-219AB]
D14  value Green  [LED_LTST-C190_G]  (hidden comment: LTST-C190KGKT)
D15  value Green  [LED_LTST-C190_G]  (hidden comment: LTST-C190KGKT)
J7  PBC02SAAN  [Sullins_PBC02SAAN]  (value not drawn)
J9  PBC02SAAN  [Sullins_PBC02SAAN]  (value not drawn)
J10  PBC02SAAN  [Sullins_PBC02SAAN]  (value not drawn)
J11  1751248  [CONN_1751248]  (value not drawn)
J13  PEC05DAAN  [CONN_PEC05DAAN]  (value not drawn)
J16  PBC02SAAN  [Sullins_PBC02SAAN]  (value not drawn)
J17  PBC02SAAN  [Sullins_PBC02SAAN]  (value not drawn)
L7  ValueDisplayed: 22µH  [WE-PD_1050]  (hidden comment: 7447714220)
Q2  2N7002  [SOT-23]
Q3  2N7002  [SOT-23]
R6  ValueDisplayed: 100k  [0603]  (hidden comment: RC0603FR-07100KL)
R53  ValueDisplayed: 49.9k  [0603]  (hidden comment: CRCW060349K9FKEA)
R54  ValueDisplayed: 887k  [0603]  (hidden comment: CRCW0603887KFKEA)
R56  ValueDisplayed: 29.4k  [0603]  (hidden comment: CRCW060329K4FKEA)
R58  ValueDisplayed: 34.0k  [0603]  (hidden comment: CRCW060334K0FKEA)
R59  ValueDisplayed: 7.50k  [0603]  (hidden comment: CRCW06037K50FKEA)
R60  ValueDisplayed: 13.3k  [0603]  (hidden comment: CRCW060313K3FKEA)
R61  ValueDisplayed: 26.7k  [0603]  (hidden comment: CRCW060326K7FKEA)
R62  ValueDisplayed: 44.2k  [0603]  (hidden comment: CRCW060344K2FKEA)
R63  ValueDisplayed: 267k  [0603]  (hidden comment: CRCW0603267KFKEA)
R64  ValueDisplayed: 93.1k  [0603]  (hidden comment: RC0603FR-0793K1L)
R67  ValueDisplayed: 150k  [0603]  (hidden comment: RC0603FR-07150KL)
R68  ValueDisplayed: 10.0k  [0603]  (hidden comment: CRCW060310K0FKEA)
R72  ValueDisplayed: 39.0k  [0603]  (hidden comment: RC0603FR-0739KL)
R73  ValueDisplayed: 63.4k  [0603]  (hidden comment: RC0603FR-0763K4L)
R74  ValueDisplayed: 37.4k  [0603]  (hidden comment: RC0603FR-0737K4L)
R88  ValueDisplayed: 102k  [0603]  (hidden comment: CRCW0603102KFKEA)
R89  ValueDisplayed: 21.5k  [0603]  (hidden comment: CRCW060321K5FKEA)
R90  ValueDisplayed: 21.5k  [0603]  (hidden comment: CRCW060321K5FKEA)
R91  ValueDisplayed: 102k  [0603]  (hidden comment: CRCW0603102KFKEA)
R92  ValueDisplayed: 21.5k  [0603]  (hidden comment: CRCW060321K5FKEA)
R93  ValueDisplayed: 21.5k  [0603]  (hidden comment: CRCW060321K5FKEA)
R96  ValueDisplayed: 0  [0603]  (hidden comment: CRCW06030000Z0EA)
R97  ValueDisplayed: 47.0k  [0603]  (hidden comment: RC0603FR-0747KL)
R98  ValueDisplayed: 47.0k  [0603]  (hidden comment: RC0603FR-0747KL)
R99  ValueDisplayed: 1.00k  [0603]  (hidden comment: ERJ-3EKF1001V)
R100  ValueDisplayed: 1.00k  [0603]  (hidden comment: ERJ-3EKF1001V)
R101  ValueDisplayed: 100k  [0603]  (hidden comment: RC0603FR-07100KL)
R102  ValueDisplayed: 100k  [0603]  (hidden comment: RC0603FR-07100KL)
S1  PTS820 J20M SMTR LFS  [SW_PTS820]  (value not drawn)
TP11  5000  [Keystone5000]  (value not drawn)
TP12  5002  [Keystone5002]  (value not drawn)
TP13  5002  [Keystone5002]  (value not drawn)
TP20  5000  [Keystone5000]  (value not drawn)
TP21  5001  [Keystone5001]  (value not drawn)
TP22  5000  [Keystone5000]  (value not drawn)
TP23  5000  [Keystone5000]  (value not drawn)
TP26  5001  [Keystone5001]  (value not drawn)
TP28  5002  [Keystone5002]  (value not drawn)
TP30  5002  [Keystone5002]  (value not drawn)
TP39  5001  [Keystone5001]  (value not drawn)
U16  TVS3300DRVR  [DRV0006A]
U17  TPS26624DRCR  [DRC0010J]
U19  TVS3300DRVR  [DRV0006A]
U20  LM76002RNPR  [RNP0030B]
U32  LMZM23600SILR  [SIL0010A]
U34  TVS1400DRVR  [DRV0006A]
U35  LMZM23600SILR  [SIL0010A]
U36  TVS1400DRVR  [DRV0006A]
U40  TVS2700DRVR  [DRV0006A]
U42  SN74LVC2G34DRLR  [DRL0006A]  (parts A,B,C of 3)

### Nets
+24V_IN: C74.1 J9.2 R64.2 U20.20(PVIN) U20.21(PVIN) U20.22(PVIN)
+24V_IN1: C101.1 C104.1 C105.1 J16.1 TP23.1 U32.3(VIN) U32.4(EN) U35.3(VIN) U35.4(EN)
DCDC_+10P5V: C102.1 C103.1 R88.2 TP20.1 U32.6(VOUT) U34.4(IN) U34.5(IN) U34.6(IN)
DCDC_-10P5V: C105.2 C106.2 C107.2 D4.2(A) Q3.2(S) R92.1 R93.1 TP22.1 U35.1(GND) U35.2(MODE/SYNC) U35.11(PAD) U36.1(GND) U36.2(GND) U36.3(GND) U36.7(PAD)
GND1: C65.2 C66.2 C68.2 C69.2 C70.1 C71.2 C72.2 C74.2 C76.2 C82.2 C83.1 C101.2 C102.2 C103.2 C104.2 C106.1 C107.1 C119.2 D4.1(C) D14.2(K) D15.2(K) J11.2 Q2.2(S) R6.2 R72.2 R73.1 R74.1 R89.1 R90.1 R91.2 R98.1 S1.1 TP21.1 TP26.1 TP39.1 U17.6(GND) U19.4(IN) U19.5(IN) U19.6(IN) U20.13(AGND) U20.14(AGND) U20.15(AGND) U20.17(SYNC/MODE) U20.24(PGND) U20.25(PGND) U20.26(PGND) U20.31(PAD) U32.1(GND) U32.2(MODE/SYNC) U32.11(PAD) U34.1(GND) U34.2(GND) U34.3(GND) U34.7(PAD) U35.6(VOUT) U36.4(IN) U36.5(IN) U36.6(IN) U40.1(GND) U40.2(GND) U40.3(GND) U40.7(PAD) U42.2(GND)
VDC_5V_1: C71.1 C72.1 C76.1 C83.2 C119.1 L7.2 R67.2 R68.2 R97.2 R101.2 R102.2 TP11.1 U20.9(BIAS) U42.5(VCC)
PG_N: Q3.1(G) R6.1 R98.2 U35.5(PGOOD)
Vin1: C65.1 J7.1 J11.1 J17.1 U16.4(IN) U16.5(IN) U16.6(IN)
Vout1: C66.1 J9.1 J10.1 J16.2 U17.10(OUT) U40.4(IN) U40.5(IN) U40.6(IN)
NetC67_1: C67.1 U17.8(DVDT)
NetC67_2: C67.2 R58.1 R59.1 R60.1 R61.1 R62.1 R63.1 U17.5(RTN) U17.11(PAD)
NetC68_1: C68.1 C69.1 J10.2
NetC70_2: C70.2 U20.8(VCC)
NetC75_1: C75.1 U20.6(CBOOT)
NetC75_2: C75.2 L7.1 U20.1(SW) U20.2(SW) U20.3(SW) U20.4(SW) U20.5(SW)
NetC82_1: C82.1 U20.11(SS/TRK)
NetD14_1: D14.1(A) R99.2
NetD15_1: D15.1(A) R100.2
NetJ7_2: J7.2 R53.2
NetJ13_1: J13.1 J13.3 J13.5 J13.7 J13.9 U17.7(ILIM)
NetJ13_2: J13.2 R59.2
NetJ13_4: J13.4 R60.2
NetJ13_6: J13.6 R61.2
NetJ13_8: J13.8 R62.2
NetJ13_10: J13.10 R63.2
NetJ17_2: J17.2 R54.2 U17.1(IN)
NetQ2_1: Q2.1(G) Q3.3(D) R101.1
NetQ2_3: Q2.3(D) R102.1 U42.3(2A)
NetR53_1: R53.1 U17.9(~{FLT})
NetR54_1: R54.1 R56.2 R96.1
NetR56_1: R56.1 R58.2 U17.3(OVP)
NetR64_1: R64.1 R73.2 U20.18(EN)
NetR67_1: R67.1 R74.2 TP13.1 U20.12(FB)
NetR68_1: R68.1 TP12.1 U20.16(PGOOD)
NetR72_1: R72.1 U20.10(RT)
NetR88_1: R88.1 R89.2 R90.2 U32.7(FB)
NetR91_1: R91.1 R92.2 R93.2 U35.7(FB)
NetR96_2: R96.2 TP28.1 U17.2(UVLO)
NetR97_1: R97.1 U32.5(PGOOD) U42.1(1A)
NetR99_1: R99.1 U42.6(1Y)
NetR100_1: R100.1 U42.4(2Y)
NetS1_2: S1.2 TP30.1 U17.4(~{SHDN})
NetU16_1: U16.1(GND) U16.2(GND) U16.3(GND) U16.7(PAD) U19.1(GND) U19.2(GND) U19.3(GND) U19.7(PAD)

Not connected (* = marked no-connect by the designer): U20 7(NC)* 19(NC)* 23(NC)* 27(NC)* 28(NC)* 29(NC)* 30(NC)*; U32 8(DNC) 9(DNC) 10(DNC); U35 8(DNC) 9(DNC) 10(DNC)

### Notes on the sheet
- 24V E-Fuse
- 24V to 5V Synchroous Stepdown Converter
- 24V to +/-10.5V Power Module

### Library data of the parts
C65 = GRM31CR72A105KA01L: CAP, CERM, 1 µF, 100 V, +/- 10%, X7R, 1206; Manufacturer: TDK Corporation; Polarized: N; CompType: Capacitor; Value: 1uF; U/M: EA; Cap_F: 0.000001; Tolerance_%: 10; Value1: Unknown; VDC_V: 100; Value2: 100V; TaMin_C: -55; TaMax_C: 125; Cap_Case: 2220; SizeArea_mm2: 5.12; SizeAreaWB_mm2: 10.92; SizeX_mm: 3.2; SizeY_mm: 1.6; SizeZ_mm: 1.8; AEC Category: Q200
C66 = GRM32ER72A225KA35L: CAP, CERM, 2.2 µF, 100 V, +/- 10%, X7R, 1210; Manufacturer: TDK Corporation; Polarized: N; CompType: Capacitor; Value: 2.2uF; U/M: EA; Cap_F: 0.0000022; Tolerance_%: 10; ESR_ohm: 0.007; Value1: 0.007 ohm; VDC_V: 100; Value2: 100V; IRMS_A: 4.4; TaMin_C: -55; TaMax_C: 125; Cap_Case: 1210; SizeArea_mm2: 8; SizeAreaWB_mm2: 14.7; SizeX_mm: 3.2; SizeY_mm: 2.5; SizeZ_mm: 2.7; AEC Category: Q200
C67 = GRM188R71C223KA01D: CAP, CERM, 0.022 µF, 16 V,+/- 10%, X7R, 0603; Manufacturer: KEMET; Polarized: N; CompType: Capacitor; Value: 0.022uF; U/M: EA; Cap_F: 0.000000022; Tolerance_%: 10; VDC_V: 16; Value2: 16V; TaMin_C: -55; TaMax_C: 125; SizeArea_mm2: 1.28; SizeAreaWB_mm2: 4.68; SizeX_mm: 1.6; SizeY_mm: 0.8; SizeZ_mm: 1; AEC Category: Q200; Green_Lifecycle: Active; Green_REACh: Passed
C68 C69 C101 C104 C105 = GRM32ER71J106KA12L: CAP, CERM, 10µF ±20% 50V Ceramic Capacitor X7R 1210; Manufacturer: Taiyo Yuden; Polarized: N; Value: 10uF; U/M: EA; Cap_F: 0.00001; Tolerance_%: 10; Value1: Unknown; VDC_V: 63; Value2: 63V; TaMin_C: -55; TaMax_C: 125; Cap_Case: 1210; SizeArea_mm2: 8; SizeAreaWB_mm2: 14.7; SizeX_mm: 3.2; SizeY_mm: 2.5; SizeZ_mm: 2.7; AEC Category: Q200
C70 = GRM188R71H104KA93D: CAP, CERM, 0.12µF ±10% 50V Ceramic Capacitor X7R 0603; Manufacturer: KEMET; Polarized: N; Value: 0.1uF; U/M: EA; Cap_F: 0.0000001; Tolerance_%: 10; VDC_V: 50; TaMin_C: -55; TaMax_C: 125; SizeArea_mm2: 1.28; SizeAreaWB_mm2: 4.68; SizeX_mm: 1.6; SizeY_mm: 0.8; SizeZ_mm: 1; AEC Category: Q200; Green_Lifecycle: Active; Green_REACh: Passed
C71 = GRM188R71E105KA12D: as C33 on sheet TIDA-010055_Non-ISO_AFE-Power+Protection _Pg5
C72 C76 = EMK107BBJ106MA-T: CAP, CERM, 10 µF, 16 V,+/- 20%, X5R, 0603; Manufacturer: Taiyo Yuden; Polarized: N; CompType: Capacitor; Value: 10uF; U/M: EA; Cap_F: 0.00001; Tolerance_%: 20; VDC_V: 16; Value2: 16V; TaMin_C: -55; TaMax_C: 85; SizeArea_mm2: 1.28; SizeAreaWB_mm2: 4.68; SizeX_mm: 1.6; SizeY_mm: 0.8; SizeZ_mm: 1; AEC Category: Q200; Green_Lifecycle: Active; Green_REACh: Passed
C74 = C1005X5R1A225K050BC: CAP CER 2.2UF 100V X7S 1206; Manufacturer: TDK Corporation; Polarized: N; CompType: Capacitor; U/M: EA; Cap_F: 0.0000022; Tolerance_%: 10; VDC_V: 100; TaMin_C: -55; TaMax_C: 125; Cap_Case: 0402; SizeArea_mm2: 0.5; SizeAreaWB_mm2: 3; SizeX_mm: 1; SizeZ_mm: 0.6; AEC Category: Q200; Green_Lifecycle: Active; Green_REACh: Passed
C75 = C2012X7R1H474K125AB: CAP, CERM, 0.47 µF, 50 V,+/- 10%, X7R, 0805; Manufacturer: Murata Electronics North America; Polarized: N; CompType: Capacitor; Value: 0.47uF; U/M: EA; Cap_F: 0.00000047; Tolerance_%: 10; ESR_ohm: 0.022012; Value1: 0.022012 ohm; VDC_V: 50; Value2: 50V; IRMS_A: 1.39566; TaMin_C: -55; TaMax_C: 125; Cap_Case: 0805; SizeArea_mm2: 2.5; SizeAreaWB_mm2: 6.75; SizeX_mm: 2; SizeY_mm: 1.25; SizeZ_mm: 1.45; AEC Category: Q200
C82 = GRM1885C1H222JA01D: CAP, CERM, 2200 pF, 50 V,+/- 5%, C0G/NP0, 0603; Manufacturer: MuRata; Polarized: N; CompType: Capacitor; Value: 2200pF; U/M: EA; Cap_F: 0.0000000022; Tolerance_%: 5; VDC_V: 50; Value2: 50V; TaMin_C: -55; TaMax_C: 125; SizeArea_mm2: 1.28; SizeAreaWB_mm2: 4.68; SizeX_mm: 1.6; SizeY_mm: 0.8; SizeZ_mm: 1; AEC Category: Q200; Green_Lifecycle: Active; Green_REACh: Passed
C83 = UMK107AB7105KA-T: CAP, CERM,  1UF 50V X5R 0603; Manufacturer: Taiyo Yuden; Polarized: N; CompType: Capacitor; U/M: EA; Cap_F: 0.000001; Tolerance_%: 10; VDC_V: 50; TempCo: X7R; TaMin_C: -55; TaMax_C: 125; SizeArea_mm2: 1.28; SizeAreaWB_mm2: 4.68; SizeX_mm: 1.6; SizeY_mm: 0.8; SizeZ_mm: 1; AEC Category: Q200; Green_Lifecycle: Active; Green_REACh: Passed
C102 C103 C106 C107 = C3216X5R1C476M160AB: CAP, CERM,47µF ±20% 16V Ceramic Capacitor JB 1206; Manufacturer: Taiyo Yuden; Polarized: N; Value: 47uF; U/M: EA; Cap_F: 0.000047; Tolerance_%: 15; VDC_V: 16; TempCo: X5R; TaMin_C: -55; TaMax_C: 85; SizeArea_mm2: 5.12; SizeAreaWB_mm2: 10.92; SizeX_mm: 3.2; SizeY_mm: 1.6; SizeZ_mm: 1.35; AEC Category: Q200; Green_Lifecycle: Active; Green_REACh: Passed
C119 = 06033D104KAT2A: as C46 on sheet TIDA-010055_Non-ISO_AFE-Power+Protection _Pg5
D4 = D_SCHOT_SL03: Diode Schottky 40V 1.1A Surface Mount DO-219AB (SMF); PartNumber: SL04-HE3-08; Manufacturer: Vishay; Area: 20000; Value: SL03
D14 D15 = LTST-C190KGKT: LED, Green, SMD; Manufacturer: Lite-On; Type: AlInGaP; Vf_V: 2; Value2: 2V; Io_A: 0.03; Tjmax_C: 85; Value1: W; U/M: EA
J7 J9 J16 J17 = PBC02SAAN: as J15 on sheet TIDA-010055_Non-ISO_AFE-Power+Protection _Pg5
J10 = PBC02SAAN: Header, 100mil, 2x1, Gold, TH; Manufacturer: Sullins Connector Solutions; U/M: EA; SymbolCreator: a0412235
J11 = 1751248: Conn Term Block, 2POS, 3.5mm, TH; Manufacturer: Phoenix Contact; CompType: Terminal Block; SymbolCreator: a0412235
J13 = PEC05DAAN: Header, 100mil, 5x2, Tin, TH; Manufacturer: Sullins Connector Solutions; SymbolCreator: a0412235; Pitch_mm: 2.54; Gender: Male; Shrouded: N; Row_Count: 2; Current_A: 3; Voltage_V: 1800; Cert_UL: Y
L7 = 7447714220: Inductor, Shielded Drum Core, Ferrite, 22 µH, 3 A, 0.042 ohm, SMD; Manufacturer: Wurth Elektronik; Value: 22uH; Ind_H: 22.0E-6; Imax_A: 3; Irms: 3A @ 40C rise; Isat: 3.6A @ 10% inductance drop; DCR_ohm: 0.042; Value2: 3A; SizeAreaWB_mm2: 144; SizeArea_mm2: 100; SizeX_mm: 10; SizeZ_mm: 5; AEC Category: Q200; Green_Lifecycle: Active; Green_REACh: Passed
Q2 Q3 = CMP-0000768-1: MOSFET, N-CH, 60 V, 115 A, SOT-23; Alternate Manufacturer: None; Manufacturer: Fairchild Semiconductor; SizeZ_mm: 1.1; ChType: N; VdsMax_V: 60V; SizeX_mm: 2.5; SizeY_mm: 3; Vgs_V: 20V; Value: 60V; SizeArea_mm2: 7.5; AEC Category: Q101; IdsMax_A: 115A; SizeAreaWB_mm2: 14; U/M: EA
R6 R101 R102 = RC0603FR-07100KL: RES, 100 k, 1%, 0.1 W, 0603; Manufacturer: Yageo America; CompType: Resistor; Value: 100k; Res_ohm: 100000; Tolerance_%: 1; Power_W: 0.1; Value2: 0.1W; VDC_V: 150; TempCo: 200 ppm/C; SizeArea_mm2: 1.28; SizeX_mm: 1.6; SizeY_mm: 0.8; EIA_Code: E96; U/M: EA; AEC Category: Q200; Green_Lifecycle: Active; Green_REACh: Passed
R53 = CRCW060349K9FKEA: RES, 49.9 k, 1%, 0.1 W, 0603; Manufacturer: Vishay-Dale; CompType: Resistor; Value: 49.9k; Res_ohm: 49900; Value_Code: 49k9; Tolerance_%: 1; Power_W: 0.1; Value2: 0.1W; VDC_V: 75; TempCo: 100 ppm/C; EIA_Code: E96; U/M: EA; SizeArea_mm2: 1.28; SizeX_mm: 1.6; SizeY_mm: 0.8; AEC Category: Q200; Green_Lifecycle: Active; Green_REACh: Passed
R54 = CRCW0603887KFKEA: RES, 887 k, 1%, 0.1 W, 0603; Manufacturer: Vishay-Dale; CompType: Resistor; Value: 887k; Res_ohm: 887000; Tolerance_%: 1; Power_W: 0.1; Value2: 0.1W; VDC_V: 75; TempCo: 100 ppm/C; SizeArea_mm2: 1.28; SizeX_mm: 1.6; SizeY_mm: 0.8; EIA_Code: E96; U/M: EA; AEC Category: Q200; Green_Lifecycle: Active; Green_REACh: Passed
R56 = CRCW060329K4FKEA: RES, 29.4 k, 1%, 0.1 W, 0603; Manufacturer: Vishay-Dale; CompType: Resistor; Value: 29.4k; Res_ohm: 29400; Value_Code: 29k4; Tolerance_%: 1; Power_W: 0.1; Value2: 0.1W; VDC_V: 75; TempCo: 100 ppm/C; SizeArea_mm2: 1.28; SizeX_mm: 1.6; SizeY_mm: 0.8; EIA_Code: E96; U/M: EA; AEC Category: Q200; Green_Lifecycle: Active; Green_REACh: Passed
R58 = CRCW060334K0FKEA: RES, 34.0 k, 1%, 0.1 W, 0603; Manufacturer: Vishay-Dale; CompType: Resistor; Value: 34.0k; Res_ohm: 34000; Value_Code: 34k0; Tolerance_%: 1; Power_W: 0.1; Value2: 0.1W; VDC_V: 75; TempCo: 100 ppm/C; EIA_Code: E96; U/M: EA; SizeArea_mm2: 1.28; SizeX_mm: 1.6; SizeY_mm: 0.8; AEC Category: Q200
R59 = CRCW06037K50FKEA: RES, 7.50 k, 1%, 0.1 W, 0603; Manufacturer: Vishay-Dale; CompType: Resistor; Value: 7.50k; Res_ohm: 7500; Value_Code: 7k50; Tolerance_%: 1; Power_W: 0.1; Value2: 0.1W; VDC_V: 75; TempCo: 100 ppm/C; SizeArea_mm2: 1.28; SizeX_mm: 1.6; SizeY_mm: 0.8; EIA_Code: E96; U/M: EA; AEC Category: Q200
R60 = CRCW060313K3FKEA: RES, 13.3 k, 1%, 0.1 W, 0603; Manufacturer: Vishay-Dale; CompType: Resistor; Value: 13.3k; Res_ohm: 13300; Value_Code: 13k3; Tolerance_%: 1; Power_W: 0.1; Value2: 0.1W; VDC_V: 75; TempCo: 100 ppm/C; SizeArea_mm2: 1.28; SizeX_mm: 1.6; SizeY_mm: 0.8; EIA_Code: E96; U/M: EA; AEC Category: Q200
R61 = CRCW060326K7FKEA: RES, 26.7 k, 1%, 0.1 W, 0603; Manufacturer: Vishay-Dale; CompType: Resistor; Value: 26.7k; Res_ohm: 26700; Value_Code: 26k7; Tolerance_%: 1; Power_W: 0.1; Value2: 0.1W; VDC_V: 75; TempCo: 100 ppm/C; SizeArea_mm2: 1.28; SizeX_mm: 1.6; SizeY_mm: 0.8; EIA_Code: E96; U/M: EA; AEC Category: Q200
R62 = CRCW060344K2FKEA: RES, 44.2 k, 1%, 0.1 W, 0603; Manufacturer: Vishay-Dale; CompType: Resistor; Value: 44.2k; Res_ohm: 44200; Value_Code: 44k2; Tolerance_%: 1; Power_W: 0.1; Value2: 0.1W; VDC_V: 75; TempCo: 100 ppm/C; SizeArea_mm2: 1.28; SizeX_mm: 1.6; SizeY_mm: 0.8; EIA_Code: E96; U/M: EA; AEC Category: Q200
R63 = CRCW0603267KFKEA: RES, 267 k, 1%, 0.1 W, 0603; Manufacturer: Vishay-Dale; CompType: Resistor; Value: 267k; Res_ohm: 267000; Tolerance_%: 1; Power_W: 0.1; Value2: 0.1W; VDC_V: 75; TempCo: 100 ppm/C; SizeArea_mm2: 1.28; SizeX_mm: 1.6; SizeY_mm: 0.8; EIA_Code: E96; U/M: EA; AEC Category: Q200
R64 = RC0603FR-0793K1L: RES, 93.1 k, 1%, 0.1 W, 0603; Manufacturer: Yageo America; CompType: Resistor; Value: 93.1k; Res_ohm: 93100; Value_Code: 93k1; Tolerance_%: 1; Power_W: 0.1; Value2: 0.1W; VDC_V: 150; TempCo: 200 ppm/C; SizeArea_mm2: 1.28; SizeX_mm: 1.6; SizeY_mm: 0.8; EIA_Code: E96; U/M: EA; AEC Category: Q200; Green_Lifecycle: Active; Green_REACh: Passed
R67 = RC0603FR-07150KL: RES, 150 k, 1%, 0.1 W, 0603; Manufacturer: Yageo America; CompType: Resistor; Value: 150k; Res_ohm: 150000; Tolerance_%: 1; Power_W: 0.1; Value2: 0.1W; VDC_V: 150; TempCo: 200 ppm/C; SizeArea_mm2: 1.28; SizeX_mm: 1.6; SizeY_mm: 0.8; EIA_Code: E96; U/M: EA; AEC Category: Q200; Green_Lifecycle: Active; Green_REACh: Passed
R68 = CRCW060310K0FKEA: RES, 10.0 k, 1%, 0.1 W, 0603; Manufacturer: Vishay-Dale; CompType: Resistor; Value: 10.0k; Res_ohm: 10000; Value_Code: 10k0; Tolerance_%: 1; Power_W: 0.1; Value2: 0.1W; VDC_V: 75; TempCo: 100 ppm/C; SizeArea_mm2: 1.28; SizeX_mm: 1.6; SizeY_mm: 0.8; EIA_Code: E96; U/M: EA; AEC Category: Q200; Green_Lifecycle: Active; Green_REACh: Passed
R72 = RC0603FR-0739KL: RES, 39.0 k, 1%, 0.1 W, 0603; Manufacturer: Yageo America; CompType: Resistor; Value: 39.0k; Res_ohm: 39000; Value_Code: 39k0; Tolerance_%: 1; Power_W: 0.1; Value2: 0.1W; VDC_V: 150; TempCo: 200 ppm/C; SizeArea_mm2: 1.28; SizeX_mm: 1.6; SizeY_mm: 0.8; U/M: EA; AEC Category: Q200; Green_Lifecycle: Active; Green_REACh: Passed
R73 = RC0603FR-0763K4L: RES, 63.4 k, 1%, 0.1 W, 0603; Manufacturer: Yageo America; CompType: Resistor; Value: 63.4k; Res_ohm: 63400; Value_Code: 63k4; Tolerance_%: 1; Power_W: 0.1; Value2: 0.1W; VDC_V: 150; TempCo: 200 ppm/C; SizeArea_mm2: 1.28; SizeX_mm: 1.6; SizeY_mm: 0.8; EIA_Code: E96; U/M: EA; AEC Category: Q200
R74 = RC0603FR-0737K4L: RES, 37.4 k, 1%, 0.1 W, 0603; Manufacturer: Yageo America; CompType: Resistor; Value: 37.4k; Res_ohm: 37400; Value_Code: 37k4; Tolerance_%: 1; Power_W: 0.1; Value2: 0.1W; VDC_V: 150; TempCo: 200 ppm/C; SizeArea_mm2: 1.28; SizeX_mm: 1.6; SizeY_mm: 0.8; EIA_Code: E96; U/M: EA; AEC Category: Q200
R88 R91 = CRCW0603102KFKEA: RES, 102 k, 1%, 0.1 W, 0603; Manufacturer: Vishay-Dale; CompType: Resistor; Value: 102k; Res_ohm: 102000; Tolerance_%: 1; Power_W: 0.1; Value2: 0.1W; VDC_V: 75; TempCo: 100 ppm/C; SizeArea_mm2: 1.28; SizeX_mm: 1.6; SizeY_mm: 0.8; EIA_Code: E96; U/M: EA; AEC Category: Q200; Green_Lifecycle: Active; Green_REACh: Passed
R89 R90 R92 R93 = CRCW060321K5FKEA: RES, 21.5 k, 1%, 0.1 W, 0603; Manufacturer: Vishay-Dale; CompType: Resistor; Value: 21.5k; Res_ohm: 21500; Value_Code: 21k5; Tolerance_%: 1; Power_W: 0.1; Value2: 0.1W; VDC_V: 75; TempCo: 100 ppm/C; SizeArea_mm2: 1.28; SizeX_mm: 1.6; SizeY_mm: 0.8; EIA_Code: E96; U/M: EA; AEC Category: Q200; Green_Lifecycle: Active; Green_REACh: Passed
R96 = CRCW06030000Z0EA: as R24 on sheet TIDA-010055_Non-ISO_AFE-Power+Protection _Pg5
R97 R98 = RC0603FR-0747KL: RES, 47.0 k, 1%, 0.1 W, 0603; Manufacturer: Yageo America; CompType: Resistor; Value: 47.0k; Res_ohm: 47000; Value_Code: 47k0; Tolerance_%: 1; Power_W: 0.1; Value2: 0.1W; VDC_V: 150; TempCo: 200 ppm/C; SizeArea_mm2: 1.28; SizeX_mm: 1.6; SizeY_mm: 0.8; U/M: EA; AEC Category: Q200; Green_Lifecycle: Active; Green_REACh: Passed
R99 R100 = ERJ-3EKF1001V: RES, 1.00 k, 1%, 0.1 W, AEC-Q200 Grade 0, 0603; Manufacturer: Panasonic; CompType: Resistor; Value: 1.00k; Res_ohm: 1000; Value_Code: 1k00; Tolerance_%: 1; Power_W: 0.1; Value2: 0.1W; VDC_V: 75; TempCo: 100 ppm/C; SizeArea_mm2: 1.28; SizeX_mm: 1.6; SizeY_mm: 0.8; EIA_Code: E96; U/M: EA; AEC Category: Q200; AEC Qualified: Y; AEC Grade: 0; Green_Lifecycle: Active; Green_REACh: Passed
S1 = PTS820 J20M SMTR LFS: Switch, SPST-NO,  Off-Mom, 0.05A, 12VDC, SMD; Manufacturer: C&K Components; SymbolCreator: a0412235; VDC_V: 12; PositionCount: 1; CurrentRating_mA: 50
TP11 TP20 TP22 TP23 = 5000: as TP5 on sheet TIDA-010055_Non-ISO_AFE-Power+Protection _Pg5
TP12 TP13 TP28 TP30 = 5002: as TP4 on sheet TIDA-010055_Non-ISO_AFE-Power+Protection _Pg5
TP21 TP26 TP39 = 5001: as TP32 on sheet TIDA-010055_Non-ISO_AFE-Power+Protection _Pg5
U16 U19 = CMP-0013424-7: 33-V Precision Surge Protection Clamp, DRV0006A (WSON-6); Manufacturer: Texas Instruments; Alternate PartNumber: TVS3300DRVT; SizeX_mm: 2; CompType: IC; SizeZ_mm: 0.8; SizeArea_mm2: 4; SizeAreaWB_mm2: 9; U/M: EA
U17 = TPS26624DRCR: 7V - 57V, 800mA Industrial eFuse with Integrated Reverse Polarity Protection, DRC0010J (VSON-10); Alternate PartNumber: TPS26625DRCR; Manufacturer: Texas Instruments; SymbolCreator: a0411947; SizeArea_mm2: 9; SizeAreaWB_mm2: 16; SizeX_mm: 3; SizeZ_mm: 1; CompType: IC; U/M: EA
U20 = LM76002RNPR: SIMPLE SWITCHER 3.5V to 60V 2.5A Synchronous Step-Down Voltage Regulator, RNP0030B (WQFN-30); Alternate PartNumber: LM76002RNPT; Manufacturer: Texas Instruments; SymbolCreator: Altium; SizeArea_mm2: 24; SizeAreaWB_mm2: 48; SizeX_mm: 4; SizeY_mm: 6; SizeZ_mm: 0.8; CompType: IC; U/M: EA
U32 U35 = CMP-0065262-5: 36-V 0.5-A Step-Down DC-DC Nano Module, SIL0010A (uSIP-10); Manufacturer: Texas Instruments; Alternate PartNumber: LMZM23600SILT; SizeX_mm: 3.8; SizeY_mm: 3.0; CompType: IC; SizeZ_mm: 1.578; SizeArea_mm2: 11.4; SizeAreaWB_mm2: 19.2; AEC Category: Q200; AEC Qualified: N
U34 U36 = CMP-0077836-1: as U38 on sheet TIDA-010055_Non-ISO_AFE-Power+Protection _Pg5
U40 = CMP-0077833-1: 27-V Precision Surge Protection Clamp, DRV0006A (WSON-6); Alternate Manufacturer: Texas Instruments; SizeAreaWB_mm2: 9.0; SizeZ_mm: 0.8; SizeX_mm: 2.0; SizeArea_mm2: 4.0; CompType: IC; AEC Qualified: N; AEC Category: Q200
U42 = CMP-0051912-2: Dual Buffer Gate, DRL0006A, LARGE T&R; Manufacturer: Texas Instruments; F @ Nom Voltage(Max)(Mhz): 150; Rating: Catalog; Sub-Family: Non-Inverting Buffer/Driver; VCC(Min)(V): 1.65; Bits(#): 2; Logic: True; 3-State Output: No; Input Type: CMOS/TTL; Output Type: CMOS; Voltage(Nom)(V): 1.8,2.5,3.3,5; VCC(Max)(V): 5.5; Output Drive (IOL/IOH)(Max)(mA): 32/-32; tpd @ Nom Voltage(Max)(ns): 8.6,4.4,4.1,3.2; ICC @ Nom Voltage(Max)(mA): 0.01; Technology Family: LVC; AEC Category: Q200; AEC Qualified: N; CompType: IC; SizeArea_mm2: 2.56; SizeX_mm: 1.6; SizeZ_mm: 0.6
